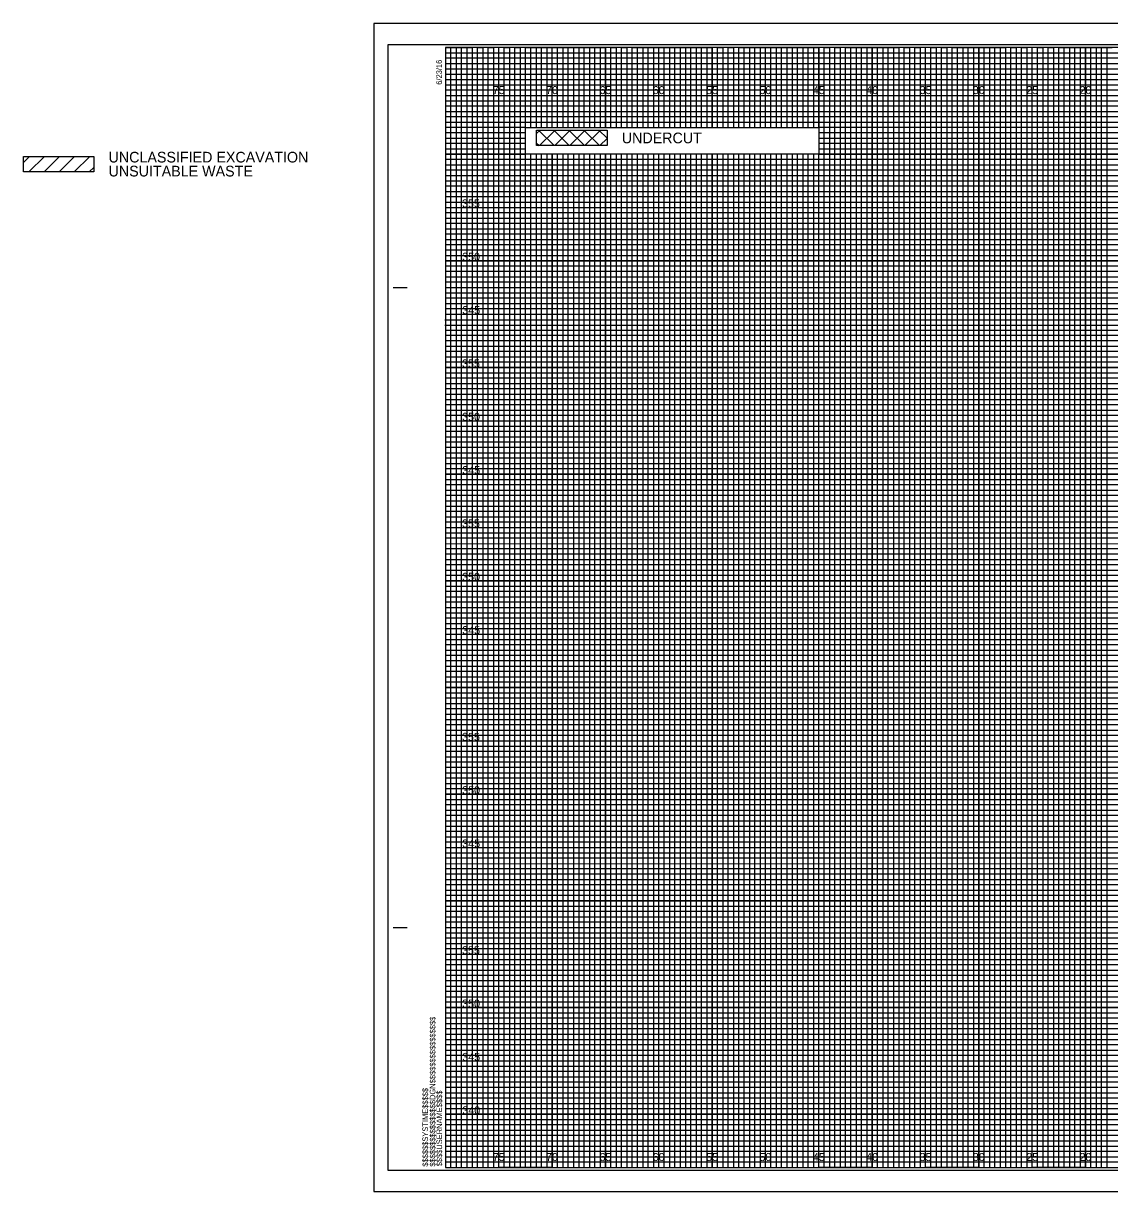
# Model space of a CAD drawing. Extents: x -40 to 162, y 548 to 657.
# Drawn here: x -39.6 to 62.2, y 547.8 to 657.2 of the extents above; entities that cross this region are included whole.
import ezdxf

# ---------------------------------------------------------------- set-up
doc = ezdxf.new("R2010")
doc.units = 0
for name, color, linetype in [('Exist DTM Drainline', 7, 'Continuous'), ('Prop XS Elevation Labels', 7, 'Continuous'), ('Prop XS Offset Labels', 7, 'Continuous'), ('Prop XS SE Text', 7, 'Continuous'), ('Sheet Cross Section CELL', 7, 'Continuous'), ('Sheet Cross Section Grid Major CELL', 7, 'Continuous'), ('Sheet Cross Section Grid Middle CELL', 7, 'Continuous'), ('Sheet Cross Section Grid Minor 1 CELL', 7, 'Continuous'), ('Sheet Cross Section Grid Minor 2 CELL', 7, 'Continuous'), ('Sheet Cutting Line CELL', 7, 'Continuous'), ('Sheet DOT Grid CELL', 7, 'Continuous'), ('Sheet Plot Border Inside CELL', 7, 'Continuous'), ('Sheet Plot Border Outside CELL', 7, 'Continuous')]:
    doc.layers.add(name, color=color, linetype=linetype)

msp = doc.modelspace()

# ---------------------------------------------------------------- linework, layer by layer
at = {"layer": 'Exist DTM Drainline'}
for p, q in [((8.55, 646.93), (8.87, 647.25)), ((8.73, 647.25), (10.19, 645.79)), ((8.83, 645.79), (10.29, 647.25)), ((10.15, 647.25), (11.61, 645.79)), ((10.24, 645.79), (11.7, 647.25)), ((11.56, 647.25), (13.02, 645.79)), ((11.65, 645.79), (13.11, 647.25)), ((12.98, 647.25), (14.44, 645.79)), ((13.07, 645.79), (14.53, 647.25)), ((14.39, 647.25), (15.15, 646.49)), ((14.48, 645.79), (15.15, 646.46)), ((8.55, 646.02), (8.78, 645.79)), ((-39.55, 644.22), (-38.99, 644.78)), ((-39.04, 643.32), (-37.58, 644.78)), ((-37.62, 643.32), (-36.16, 644.78)), ((-36.21, 643.32), (-34.75, 644.78)), ((-34.8, 643.32), (-33.34, 644.78)), ((-33.38, 643.32), (-32.96, 643.75))]:
    msp.add_line(p, q, dxfattribs=at)
for points in [[(7.5, 647.5), (35, 647.5), (35, 645), (7.5, 645)], [(8.55, 647.25), (15.15, 647.25), (15.15, 645.79), (8.55, 645.79)], [(-39.55, 644.78), (-32.96, 644.78), (-32.96, 643.32), (-39.55, 643.32)]]:
    msp.add_lwpolyline(points, close=True, dxfattribs=at)
at = {"layer": 'Sheet Cross Section CELL'}
for p, q in [((-4.9, 632.5), (-3.65, 632.5)), ((-4.85, 632.5), (-3.6, 632.5)), ((-4.9, 572.5), (-3.65, 572.5)), ((-4.85, 572.5), (-3.6, 572.5)), ((0, 550), (0, 550)), ((0, 550), (0, 550)), ((0, 550), (0, 550)), ((0, 550), (0, 550)), ((0, 550), (0, 550)), ((0, 550), (0, 550)), ((0, 550), (0, 550))]:
    msp.add_line(p, q, dxfattribs=at)
msp.add_lwpolyline([(160, 655), (0, 655), (0, 550), (160, 550)], close=True, dxfattribs=at)
at = {"layer": 'Sheet Cross Section Grid Major CELL'}
for p, q in [((5, 655), (0, 655)), ((5, 550), (5, 655)), ((10, 647.5), (10, 655)), ((10, 655), (15, 655)), ((15, 655), (15, 647.5)), ((20, 647.5), (20, 655)), ((20, 655), (25, 655)), ((25, 655), (25, 647.5)), ((30, 647.5), (30, 655)), ((30, 655), (35, 655)), ((35, 655), (35, 647.5)), ((45, 655), (40, 655)), ((40, 655), (40, 550)), ((45, 550), (45, 655)), ((55, 655), (50, 655)), ((50, 655), (50, 550)), ((55, 550), (55, 655)), ((65, 655), (60, 655)), ((60, 655), (60, 550)), ((10, 645), (10, 550)), ((15, 645), (15, 550)), ((20, 550), (20, 645)), ((25, 645), (25, 550)), ((30, 550), (30, 645)), ((35, 550), (35, 645)), ((10, 550), (5, 550)), ((15, 550), (20, 550)), ((25, 550), (30, 550)), ((40, 550), (35, 550)), ((50, 550), (45, 550)), ((60, 550), (55, 550))]:
    msp.add_line(p, q, dxfattribs=at)
for points in [[(0, 650), (160, 650), (160, 645), (35, 645)], [(7.5, 645), (0, 645)], [(0, 640), (160, 640), (160, 635), (0, 635)], [(0, 630), (160, 630), (160, 625), (0, 625)], [(0, 620), (160, 620), (160, 615), (0, 615)], [(0, 610), (160, 610), (160, 605), (0, 605)], [(0, 600), (160, 600), (160, 595), (0, 595)], [(0, 590), (160, 590), (160, 585), (0, 585)], [(0, 580), (160, 580), (160, 575), (0, 575)], [(0, 570), (160, 570), (160, 565), (0, 565)], [(0, 560), (160, 560), (160, 555), (0, 555)]]:
    msp.add_lwpolyline(points, dxfattribs=at)
at = {"layer": 'Sheet Cross Section Grid Middle CELL'}
for points in [[(0, 655), (2.5, 655), (2.5, 550), (7.5, 550), (7.5, 645)], [(7.5, 647.5), (7.5, 655), (12.5, 655), (12.5, 647.5)], [(17.5, 647.5), (17.5, 655), (22.5, 655), (22.5, 647.5)], [(27.5, 647.5), (27.5, 655), (32.5, 655), (32.5, 647.5)], [(32.5, 645), (32.5, 550), (37.5, 550), (37.5, 655), (42.5, 655), (42.5, 550), (47.5, 550), (47.5, 655), (52.5, 655), (52.5, 550), (57.5, 550), (57.5, 655), (62.5, 655)], [(0, 652.5), (137.5, 652.5)], [(7.5, 647.5), (0, 647.5)], [(35, 642.5), (160, 642.5), (160, 647.5), (35, 647.5)], [(12.5, 645), (12.5, 550), (17.5, 550), (17.5, 645)], [(22.5, 645), (22.5, 550), (27.5, 550), (27.5, 645)], [(0, 642.5), (35, 642.5)], [(0, 632.5), (160, 632.5), (160, 637.5), (0, 637.5)], [(0, 622.5), (160, 622.5), (160, 627.5), (0, 627.5)], [(0, 612.5), (160, 612.5), (160, 617.5), (0, 617.5)], [(0, 602.5), (160, 602.5), (160, 607.5), (0, 607.5)], [(0, 592.5), (160, 592.5), (160, 597.5), (0, 597.5)], [(0, 582.5), (160, 582.5), (160, 587.5), (0, 587.5)], [(0, 572.5), (160, 572.5), (160, 577.5), (0, 577.5)], [(0, 562.5), (160, 562.5), (160, 567.5), (0, 567.5)], [(0, 552.5), (160, 552.5), (160, 557.5), (0, 557.5)]]:
    msp.add_lwpolyline(points, dxfattribs=at)
at = {"layer": 'Sheet Cross Section Grid Minor 1 CELL'}
for p, q in [((0, 654.5), (130, 654.5)), ((130, 653.99), (0, 653.99)), ((0, 653.99), (0, 653.5)), ((0, 653.5), (130, 653.5)), ((130, 652.95), (0, 652.95)), ((0, 652.95), (0, 652)), ((0, 652), (160, 652))]:
    msp.add_line(p, q, dxfattribs=at)
for points in [[(0, 651.5), (135, 651.5), (160, 651.5), (160, 651), (0, 651)], [(0, 650.5), (160, 650.5), (160, 649.5), (0, 649.5)], [(0, 649), (160, 649), (160, 648.5), (0, 648.49)], [(0, 648), (160, 648), (160, 647), (35, 647)], [(7.5, 647), (0, 647)], [(0, 646.5), (7.5, 646.5)], [(35, 646.5), (160, 646.5), (160, 646), (35, 646)], [(7.5, 646), (0, 646)], [(0, 645.5), (7.5, 645.5)], [(35, 645.5), (160, 645.5), (160, 644.5), (35, 644.5)], [(35, 644.5), (0, 644.5)], [(0, 644), (35, 644)], [(35, 644), (160, 644), (160, 643.5), (35, 643.5)], [(35, 643.5), (0, 643.5)], [(0, 643), (35, 643)], [(35, 643), (160, 643), (160, 642), (0, 642)], [(0, 641.5), (160, 641.5), (160, 641), (0, 641)], [(0, 640.5), (160, 640.5), (160, 639.5), (0, 639.5)], [(0, 639), (160, 639), (160, 638.5), (0, 638.5)], [(0, 638), (160, 638), (160, 636.98), (160, 636.5), (160, 636), (0, 636)], [(0, 637), (160, 637), (160, 636.5), (0, 636.5)], [(0, 635.5), (160, 635.5), (160, 634.5), (0, 634.51)], [(0, 634.51), (160, 634.5), (160, 634), (0, 634)], [(0, 633.5), (160, 633.5), (160, 633), (0, 633)], [(0, 632), (160, 632), (160, 631.5), (0, 631.5)], [(0, 631), (160, 631), (160, 630.5), (0, 630.5)], [(-0.04, 629.45), (160, 629.45), (160, 628.94), (-0.04, 628.94)], [(0, 628.5), (160, 628.5), (160, 628), (0, 628)], [(0, 627), (160, 627), (160, 626.5), (0, 626.5)], [(0, 626), (160, 626), (160, 625.5), (0, 625.5)], [(0, 624.5), (160, 624.5), (160, 624), (0, 624)], [(0, 623.5), (160, 623.5), (160, 623), (0, 623)], [(0, 622), (160, 622), (160, 621.5), (0, 621.5)], [(0, 621), (160, 621), (160, 620.5), (0, 620.5)], [(0, 619.5), (160, 619.5), (160, 618.99), (0, 619)], [(0, 618.5), (160, 618.5), (160, 618), (0, 618)], [(0, 617), (160, 617), (160, 616.5), (0, 616.5)], [(0, 616), (160, 616), (160, 615.5), (0, 615.5)], [(0, 614.5), (160, 614.5), (160, 614), (0, 614)], [(0, 613.5), (160, 613.5), (160, 613), (0, 613)], [(0, 612), (160, 612), (160, 611.5), (0, 611.5)], [(0, 611), (160, 611), (160, 610.5), (0, 610.5)], [(0, 609.5), (160, 609.5), (160, 609), (0, 609)], [(0, 608.5), (160.03, 608.46), (160, 608), (0, 608)], [(0, 607), (160, 607), (160, 606.5), (0, 606.5)], [(0, 606), (160, 606), (160, 605.5), (0, 605.5)], [(0, 604.5), (160, 604.5), (160, 604), (0, 604)], [(0, 603.5), (160, 603.5), (160, 603), (0, 603)], [(0, 602), (160, 602), (160, 601.5), (0, 601.5)], [(0, 601), (160, 601), (160, 600.5), (0, 600.5)], [(0, 599.5), (160, 599.5), (160, 599), (0, 599)], [(0, 598.5), (160, 598.5), (160, 598), (0, 598)], [(0, 597), (160, 597), (160, 596.5), (0, 596.5)], [(0, 596), (160, 596), (160, 595.5), (0, 595.5)], [(0, 594.5), (160, 594.5), (160, 594), (0, 594)], [(0, 593.5), (160, 593.5), (160, 593), (0, 593)], [(0, 592), (160, 592), (160, 591.5), (0, 591.5)], [(0, 591), (160, 591), (160, 590.5), (0, 590.5)], [(0, 589.5), (160, 589.5), (160, 588.99), (0, 589)], [(0, 588.5), (160, 588.5), (160, 588), (0, 588)], [(0, 587), (160, 587), (160, 586.5), (0, 586.5)], [(0, 586), (160, 586), (160, 585.5), (0, 585.5)], [(0, 584.5), (160, 584.5), (160, 584), (0, 584)], [(0, 583.5), (160, 583.5), (160, 583), (0, 583)], [(0, 582), (160, 582), (160, 581.5), (0, 581.5)], [(0, 581), (160, 581), (160, 580.5), (0, 580.5)], [(0, 579.5), (160, 579.5), (160, 579), (0, 579)], [(0, 578.5), (160.03, 578.46), (160, 578), (0, 578)], [(0, 577), (160, 577), (160, 576.5), (0, 576.5)], [(0, 576), (160, 576), (160, 575.5), (0, 575.5)], [(0, 574.5), (160, 574.5), (160, 574), (0, 574)], [(0, 573.5), (160, 573.5), (160, 573), (0, 573)], [(0, 572), (160, 572), (160, 571.5), (0, 571.5)], [(0, 571), (160, 571), (160, 570.5), (0, 570.5)], [(0, 569.5), (160, 569.5), (160, 569), (0, 569)], [(0, 568.5), (160, 568.5), (160, 568), (0, 568)], [(0, 567), (160, 567), (160, 566.5), (0, 566.5)], [(0, 566), (160, 566), (160, 565.5), (0, 565.5)], [(0, 564.5), (160, 564.5), (160, 564), (0, 564)], [(0, 563.5), (160, 563.5), (160, 563), (0, 563)], [(0, 562), (160, 562), (160, 561.5), (0, 561.5)], [(0, 561), (160, 561), (160, 560.5), (0, 560.5)], [(0, 559.5), (160, 559.5), (160, 559), (0, 559)], [(0, 558.5), (160, 558.5), (160, 558), (0, 558)], [(0, 557), (160, 557), (160, 556.5), (0, 556.5)], [(0, 556), (160, 556), (160, 555.5), (0, 555.5)], [(0, 554.5), (160, 554.5), (160, 554), (0, 554)], [(0, 553.5), (160, 553.5), (160, 553), (0, 553)], [(0, 552), (160, 552), (160, 551.5), (0, 551.5)], [(0, 551), (160, 551), (160, 550.5), (0, 550.5)]]:
    msp.add_lwpolyline(points, dxfattribs=at)
at = {"layer": 'Sheet Cross Section Grid Minor 2 CELL'}
for points in [[(0, 550), (0.5, 550), (0.5, 655), (1, 655), (1, 550)], [(1, 550), (1.5, 550), (1.5, 655), (2, 655), (2, 550)], [(2.5, 550), (3, 550), (3, 655), (3.5, 655), (3.5, 550)], [(3.5, 550), (4, 550), (4, 655), (4.5, 655), (4.5, 550)], [(5, 550), (5.5, 550), (5.5, 655), (6, 655), (6, 550)], [(6, 550), (6.5, 550), (6.5, 655), (7, 655), (7, 550)], [(8, 647.5), (8, 655), (8.5, 655), (8.5, 647.5)], [(9, 647.5), (9, 655), (9.5, 655), (9.5, 647.5)], [(10.5, 647.5), (10.5, 655), (11, 655), (11, 647.5)], [(11.5, 647.5), (11.5, 655), (12, 655), (12, 647.5)], [(13, 647.5), (13, 655), (13.5, 655), (13.5, 647.5)], [(14, 647.5), (14, 655), (14.5, 655), (14.5, 647.5)], [(15.5, 647.5), (15.5, 655), (16, 655), (16, 647.5)], [(16.5, 647.5), (16.5, 655), (17, 655), (17, 647.5)], [(18, 647.5), (18, 655), (18.5, 655), (18.5, 647.5)], [(19, 647.5), (19, 655), (19.5, 655), (19.5, 647.5)], [(20.5, 647.5), (20.5, 655), (21, 655), (21, 647.5)], [(21.5, 647.5), (21.5, 655), (22, 655), (22, 647.5)], [(23, 647.5), (23, 655), (23.5, 655), (23.5, 647.5)], [(24, 647.5), (24, 655), (24.5, 655), (24.5, 647.5)], [(25.5, 647.5), (25.5, 655), (26, 655), (26, 647.5)], [(26.5, 647.5), (26.5, 655), (27, 655), (27, 647.5)], [(28, 647.5), (28, 655), (28.5, 655), (28.5, 647.5)], [(29, 647.5), (29, 655), (29.5, 655), (29.5, 647.5)], [(30.5, 647.5), (30.5, 655), (31, 655), (31, 647.5)], [(31.5, 647.5), (31.5, 655), (32, 655), (32, 647.5)], [(33, 647.5), (33, 655), (33.5, 655), (33.5, 647.5)], [(34, 647.5), (34, 655), (34.5, 655), (34.5, 647.5)], [(35, 550), (35.5, 550), (35.5, 655), (36, 655), (36, 550)], [(36, 550), (36.5, 550), (36.5, 655), (37, 655), (37, 550)], [(37.5, 550), (38, 550), (38, 655), (38.5, 655), (38.5, 550)], [(38.5, 550), (39, 550), (39, 655), (39.5, 655), (39.5, 550)], [(40, 550), (40.5, 550), (40.5, 655), (41, 655), (41, 550)], [(41, 550), (41.5, 550), (41.5, 655), (42, 655), (42, 550)], [(42.5, 550), (43, 550), (43, 655), (43.5, 655), (43.5, 550)], [(43.5, 550), (44, 550), (44, 655), (44.5, 655), (44.5, 550)], [(45, 550), (45.5, 550), (45.5, 655), (46, 655), (46, 550)], [(46, 550), (46.5, 550), (46.5, 655), (47, 655), (47, 550)], [(47.5, 550), (48, 550), (48, 655), (48.5, 655), (48.5, 550)], [(48.5, 550), (49, 550), (49, 655), (49.5, 655), (49.5, 550)], [(50, 550), (50.5, 550), (50.5, 655), (51, 655), (51, 550)], [(51, 550), (51.5, 550), (51.5, 655), (52, 655), (52, 550)], [(52.5, 550), (53, 550), (53, 655), (53.5, 655), (53.5, 550)], [(53.5, 550), (54, 550), (54, 655), (54.5, 655), (54.5, 550)], [(55, 550), (55.5, 550), (55.5, 655), (56, 655), (56, 550)], [(56, 550), (56.5, 550), (56.5, 655), (57, 655), (57, 550)], [(57.5, 550), (58, 550), (58, 655), (58.5, 655), (58.5, 550)], [(58.5, 550), (59, 550), (59, 655), (59.5, 655), (59.5, 550)], [(60, 550), (60.5, 550), (60.5, 655), (61, 655), (61, 550)], [(61, 550), (61.5, 550), (61.5, 655), (62, 655), (62, 550)], [(7.5, 550), (8, 550), (8, 645)], [(8.5, 645), (8.5, 550)], [(8.5, 550), (9, 550), (9, 645)], [(9.5, 645), (9.5, 550)], [(10, 550), (10.5, 550), (10.5, 645)], [(11, 645), (11, 550)], [(11, 550), (11.5, 550), (11.5, 645)], [(12, 645), (12, 550)], [(12.5, 550), (13, 550), (13, 645)], [(13.5, 645), (13.5, 550)], [(13.5, 550), (14, 550), (14, 645)], [(14.5, 645), (14.5, 550)], [(15, 550), (15.5, 550), (15.5, 645)], [(16, 645), (16, 550)], [(16, 550), (16.5, 550), (16.5, 645)], [(17, 645), (17, 550)], [(17.5, 550), (18, 550), (18, 645)], [(18.5, 645), (18.5, 550)], [(18.5, 550), (19, 550), (19, 645)], [(19.5, 645), (19.5, 550)], [(20, 550), (20.5, 550), (20.5, 645)], [(21, 645), (21, 550)], [(21, 550), (21.5, 550), (21.5, 645)], [(22, 645), (22, 550)], [(22.5, 550), (23, 550), (23, 645)], [(23.5, 645), (23.5, 550)], [(23.5, 550), (24, 550), (24, 645)], [(24.5, 645), (24.5, 550)], [(25, 550), (25.5, 550), (25.5, 645)], [(26, 645), (26, 550)], [(26, 550), (26.5, 550), (26.5, 645)], [(27, 645), (27, 550)], [(27.5, 550), (28, 550), (28, 645)], [(28.5, 645), (28.5, 550)], [(28.5, 550), (29, 550), (29, 645)], [(29.5, 645), (29.5, 550)], [(30, 550), (30.5, 550), (30.5, 645)], [(31, 645), (31, 550)], [(31, 550), (31.5, 550), (31.5, 645)], [(32, 645), (32, 550)], [(32.5, 550), (33, 550), (33, 645)], [(33.5, 645), (33.5, 550)], [(33.5, 550), (34, 550), (34, 645)], [(34.5, 645), (34.5, 550)]]:
    msp.add_lwpolyline(points, dxfattribs=at)
at = {"layer": 'Sheet Cutting Line CELL'}
for p, q in [((161.65, 657.25), (-6.7, 657.25)), ((-6.7, 657.25), (-6.7, 547.75)), ((-6.7, 547.75), (161.65, 547.75))]:
    msp.add_line(p, q, dxfattribs=at)
at = {"layer": 'Sheet DOT Grid CELL'}
for p, q in [((5, 550), (5, 655)), ((10, 647.5), (10, 655)), ((15, 647.5), (15, 655)), ((20, 647.5), (20, 655)), ((25, 647.5), (25, 655)), ((30, 647.5), (30, 655)), ((35, 647.5), (35, 655)), ((40, 550), (40, 655)), ((45, 550), (45, 655)), ((50, 550), (50, 655)), ((55, 550), (55, 655)), ((60, 550), (60, 655)), ((0, 650), (160, 650)), ((0, 645), (7.5, 645)), ((10, 550), (10, 645)), ((15, 550), (15, 645)), ((20, 550), (20, 645)), ((25, 550), (25, 645)), ((30, 550), (30, 645)), ((35, 645), (160, 645)), ((0, 640), (160, 640)), ((0, 635), (160, 635)), ((0, 630), (160, 630)), ((0, 625), (160, 625)), ((0, 620), (160, 620)), ((0, 615), (160, 615)), ((0, 610), (160, 610)), ((0, 605), (160, 605)), ((0, 600), (160, 600)), ((0, 595), (160, 595)), ((0, 590), (160, 590)), ((0, 585), (160, 585)), ((0, 580), (160, 580)), ((0, 575), (160, 575)), ((0, 570), (160, 570)), ((0, 565), (160, 565)), ((0, 560), (160, 560)), ((0, 555), (160, 555))]:
    msp.add_line(p, q, dxfattribs=at)
at = {"layer": 'Sheet Plot Border Inside CELL'}
msp.add_lwpolyline([(-5.4, 549.75), (161.2, 549.75), (161.2, 655.25), (-5.4, 655.25)], close=True, dxfattribs=at)
at = {"layer": 'Sheet Plot Border Outside CELL'}
msp.add_lwpolyline([(-6.7, 547.75), (161.65, 547.75), (161.65, 657.25), (-6.7, 657.25)], close=True, dxfattribs=at)

# ---------------------------------------------------------------- texts
at = {"layer": 'Prop XS Elevation Labels'}
for s, p in [('355', (1.56, 640)), ('350', (1.57, 635)), ('345', (1.58, 630)), ('355', (1.56, 625)), ('350', (1.57, 620)), ('345', (1.58, 615)), ('355', (1.56, 610)), ('350', (1.57, 605)), ('345', (1.58, 600)), ('355', (1.56, 590)), ('350', (1.57, 585)), ('345', (1.58, 580)), ('355', (1.56, 570)), ('350', (1.57, 565)), ('345', (1.58, 560)), ('340', (1.59, 555))]:
    msp.add_text(s, height=0.75, dxfattribs=at).set_placement(p)
at = {"layer": 'Prop XS Offset Labels'}
for s, p in [('75', (4.44, 650.62)), ('70', (9.43, 650.62)), ('65', (14.44, 650.62)), ('60', (19.43, 650.62)), ('55', (24.44, 650.62)), ('50', (29.43, 650.62)), ('45', (34.44, 650.62)), ('40', (39.43, 650.62)), ('35', (44.44, 650.62)), ('30', (49.43, 650.62)), ('25', (54.44, 650.62)), ('20', (59.43, 650.62)), ('75', (4.44, 550.62)), ('70', (9.43, 550.62)), ('65', (14.44, 550.62)), ('60', (19.43, 550.62)), ('55', (24.44, 550.62)), ('50', (29.43, 550.62)), ('45', (34.44, 550.62)), ('40', (39.43, 550.62)), ('35', (44.44, 550.62)), ('30', (49.43, 550.62)), ('25', (54.44, 550.62)), ('20', (59.43, 550.62))]:
    msp.add_text(s, height=0.75, dxfattribs=at).set_placement(p)
at = {"layer": 'Prop XS SE Text'}
for s, p in [('UNDERCUT', (16.53, 646.01)), ('UNCLASSIFIED EXCAVATION', (-31.57, 644.21)), ('UNSUITABLE WASTE', (-31.57, 642.9))]:
    msp.add_text(s, height=1, dxfattribs=at).set_placement(p)
at = {"layer": 'Sheet Cross Section CELL'}
for s, p in [('6/23/16', (-0.33, 651.5)), ('$$$$$$$$$$$$$$$$DGN$$$$$$$$$$$$$$$$', (-0.94, 550.09)), ('$$$$$$SYSTIME$$$$$', (-1.63, 550.09)), ('$$$$USERNAME$$$$', (-0.31, 550.12))]:
    msp.add_text(s, height=0.525, rotation=90, dxfattribs=at).set_placement(p)

doc.saveas('drawing.dxf')
